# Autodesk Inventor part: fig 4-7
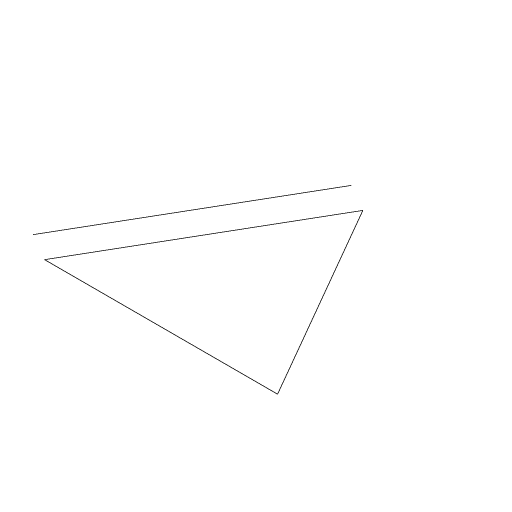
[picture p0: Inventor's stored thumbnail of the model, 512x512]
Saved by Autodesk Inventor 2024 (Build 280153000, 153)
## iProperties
Created: 2005-02
Part Number: fig 4-7
Document SubType Name: Modeling
Designer: CADCIM
Manufacturer: Standard
Standards Organization: Custom
Density: 1 g/cm^3
Material: Generic
Appearance: Default
Author: CADCIM
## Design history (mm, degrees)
sketch "Sketch1"
  geometry: L1 (-3.883, 28.419)-(-24.946, -8.063); L2 (-24.946, -8.063)-(17.18, -8.063); L3 (17.18, -8.063)-(-3.883, 28.419); L4 (-8.847, 31.285)-(-29.909, -5.197)
  constraints: 8 end point, 2 equal length, 1 horizontal, 1 parallel, 1 other
